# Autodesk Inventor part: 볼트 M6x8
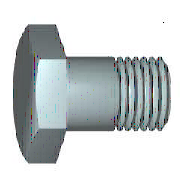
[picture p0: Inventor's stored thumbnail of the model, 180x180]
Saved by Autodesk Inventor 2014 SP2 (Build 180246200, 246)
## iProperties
Created: 2012-02
Part Number: 볼트 M6x8
Material: 강철, 연강
Description: 6각 머리 볼트 및 6각 머리 나사
Document SubType Name: Modeling
Standard: KS B 1002
Designer: mduedu
Standards Organization: KS
Language: ko-KR
Size Designation: C  M 6 x 12
Categories: <MemberInstance><Categories><Category DisplayName="조임쇠" InternalName="e4da775c-781d-43d5-af7c-5136215cf5a6" Mnemonic="FSTN"><Category DisplayName="볼트" InternalN
Density: 1 g/cm^3
Appearance: 강철
IsCustomPart: 1
Author: mduedu
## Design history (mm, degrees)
sketch "스케치1"
  geometry: L1 (0, 3)-(8, 3); L2 (8, 3)-(8, 0); L3 (8, 0)-(0, 0); L4 (-2.4, 0)-(14.4, 0) reference; L5 (0, -0.6)-(0, 3.6) reference; L6 (0, 3)-(0, 0)
  constraints: 8 end point, 3 point on line, 1 collinear
  dimensions: "d2" = 6 diameter of L1 L3 (= GD); "d59" = 8 distance between parallel lines of L2 L5 (= NLG)
revolve "본체" sketch "스케치1" stored, may be unused: angle "d12" = 90 deg
sketch "스케치2"
  geometry: L1 (0, 5.774)-(5, 2.887); L2 (5, 2.887)-(5, -2.887); L3 (5, -2.887)-(0, -5.774); L4 (0, -5.774)-(-5, -2.887); L5 (-5, -2.887)-(-5, 2.887); L6 (-5, 2.887)-(0, 5.774); L7 (-7, 0)-(7, 0) reference; L8 (0, 8.083)-(0, -8.083) reference; 2 further points
  constraints: 12 end point, 2 midpoint, 1 coincident, 1 vertical, 11 other
  dimensions: "d11" = 10 distance between parallel lines of L5 L2 (= SW)
extrude "머리" join sketch "스케치2" distance "d3" = 4 (= KOH); taper "d4" = 0 deg
revolve "모따기1" stored, may be unused: angle "d21" = 90 deg
workplane "Work Plane1"
body "Solid1"
feature "스레드" dims "d15" = 9 (= GEL), "d16" = 0
chamfer "모따기2" distance "d6" = 0.61345 (= -0.5 x SPD + 0.5 x GD); stored, may be unused: second distance "d7" = 0.61355 (computed from GUL), angle "d55" = 45 deg
sketch "스케치4"
  geometry: L1 (-3.423, 6)-(-4, 5); L2 (-1.1, 0)-(-0.234, 0); L3 (-4.753, 0)-(0.519, 0) reference; L4 (-4, 6)-(-3.423, 6); L5 (-4, 5)-(-4, 6); L6 (0, 7.2)-(0, -1.2) reference
  constraints: 8 end point, 1 parallel, 1 perpendicular, 1 point on line
  dimensions: "d65" = 10 diameter of L1.end L2 (= SW); "d67" = 30 deg angle of L1 L5 (= ANG1); "d68" = 12 diameter of L4 L2 (= 1.2 x SW); "d69" = 4 distance between parallel lines of L5 L6 (= KOH)
other parameters: "NLG" = 8 [user parameter; used in 1 equation term], "GD" = 6 (= NND) [user parameter; used in 2 equation terms], "BDM" = 6 (= NND) [user parameter], "KOH" = 4 [user parameter; used in 2 equation terms], "GEL" = 9 [user parameter; used in 1 equation term], "SW" = 10 [user parameter; used in 5 equation terms], "SPD" = 4.7731 (= NND - 1.2269 x PTC) [user parameter; used in 1 equation term], "SD2" = 6 (= NND) [user parameter], "SD" = 0 [user parameter], "ANG1" = 30 deg [user parameter; used in 1 equation term], "GAL" = 0.61345 (= 0.61345 x PTC) [user parameter], "GUL" = 0.61345 (= 0.61345 x PTC) [user parameter; used in 1 equation term], "d8" = 0, "RR" = 0.25 [user parameter], "d58" = 0, "RR1" = 0.1 [user parameter], "GD1" = 4.7731 (= THREADDIA - 1.2269 x PTC) [user parameter], "THREADDIA" = 6 [user parameter; used in 1 equation term], "TOA" = 30 deg [user parameter], "PTC" = 1 [user parameter; used in 5 equation terms], "NND" = 6 [user parameter; used in 4 equation terms], "E0" = 11.55 (= 1.155 x SW) [user parameter]
